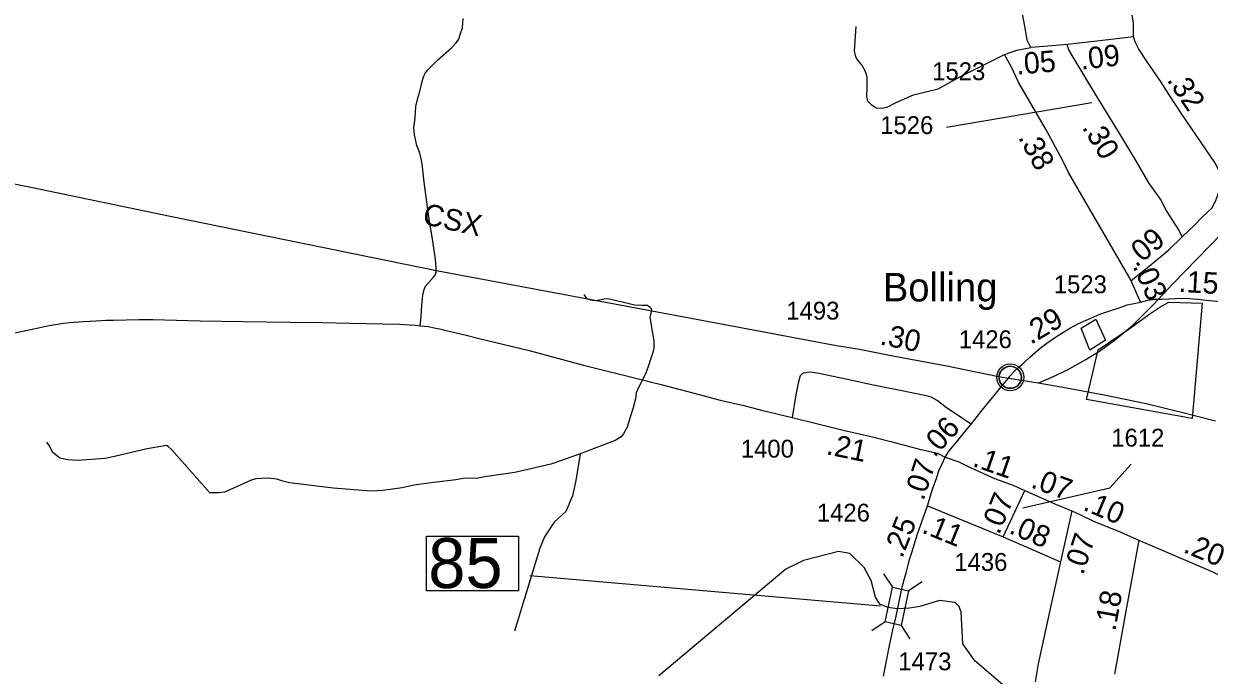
# Model space of a CAD drawing. Extents: x 2290615 to 2522933, y 819489 to 1012715.
# Drawn here: x 2377563 to 2385868, y 989250 to 993811 of the extents above; entities that cross this region are included whole.
import ezdxf

# ---------------------------------------------------------------- set-up
doc = ezdxf.new("R2010")
doc.units = 0
for name, color, linetype in [('Exist Boundary Political City Limit New', 7, 'Continuous'), ('Exist Boundary Political City Limit Old', 7, 'Continuous'), ('Exist Civil Demographics City Label', 7, 'Continuous'), ('Exist Civil Demographics Community CELL', 7, 'Continuous'), ('Exist Hydrographic Creek Single Shore', 7, 'Continuous'), ('Exist Railroad Mainline', 7, 'Continuous'), ('Exist Railroad Mainline Label', 7, 'Continuous'), ('Exist Road Non-System Type 51', 7, 'Continuous'), ('Exist Road Secondary Mileage Hundredths English Label', 7, 'Continuous'), ('Exist Road Secondary Mileage Tenths English Label', 7, 'Continuous'), ('Exist Road Secondary Structure Standard Bridge CELL', 7, 'Continuous'), ('Exist Road Secondary Structure Standard Bridge Number Label', 7, 'Continuous'), ('Exist Road Secondary Type 51 Attributed', 7, 'Continuous'), ('Exist Road Secondary Type 51 Number Label', 7, 'Continuous'), ('Map Preparation Boundary City Limit Buffer Line', 7, 'Continuous')]:
    doc.layers.add(name, color=color, linetype=linetype)

msp = doc.modelspace()

# ---------------------------------------------------------------- linework, layer by layer
at = {"layer": 'Exist Boundary Political City Limit New'}
for points in [[(2385584.2, 991862), (2385818.4, 991856), (2385747.9, 991048.3), (2385009.2, 991181), (2385090.8, 991527.1), (2385307.2, 991674.3), (2385452.8, 991779.2), (2385521.6, 991826.1), (2385584.2, 991862)], [(2385074.3, 991742.2), (2385141.2, 991595.5), (2385031, 991526.2), (2384969.9, 991680.3), (2385074.3, 991742.2)]]:
    msp.add_lwpolyline(points, dxfattribs=at)
at = {"layer": 'Exist Boundary Political City Limit Old'}
for points in [[(2385584.2, 991862), (2385818.4, 991856), (2385747.9, 991048.3), (2385009.2, 991181), (2385090.8, 991527.1), (2385307.2, 991674.3), (2385452.8, 991779.2), (2385521.6, 991826.1), (2385584.2, 991862)], [(2385074.3, 991742.2), (2385141.2, 991595.5), (2385031, 991526.2), (2384969.9, 991680.3), (2385074.3, 991742.2)]]:
    msp.add_lwpolyline(points, dxfattribs=at)
at = {"layer": 'Exist Civil Demographics Community CELL'}
msp.add_lwpolyline([(2384396.5, 991348.2), (2384397.4, 991353.8), (2384399.2, 991360.4), (2384402.1, 991367.6), (2384405.1, 991373.3), (2384408.4, 991379.1), (2384412.2, 991384.2), (2384416.1, 991388.6), (2384420.7, 991393.2), (2384426.2, 991397.7), (2384431.7, 991401.4), (2384436.6, 991404.3), (2384441.6, 991406.7), (2384447.1, 991409), (2384452.7, 991410.8), (2384457, 991412), (2384461.9, 991412.7), (2384466, 991413.5), (2384472.4, 991413.7), (2384476.8, 991413.6), (2384482.5, 991413.3), (2384487.4, 991412.6), (2384492.3, 991411.6), (2384497.3, 991410.2), (2384502.5, 991408.3), (2384509.1, 991405.4), (2384515.4, 991401.9), (2384520.4, 991398.3), (2384525.6, 991394.3), (2384528.9, 991391.2), (2384533, 991386.8), (2384536.9, 991382.1), (2384540, 991377.5), (2384543.1, 991372.5), (2384545.6, 991367.3), (2384547.6, 991362.3), (2384549.2, 991357.3), (2384550.4, 991352.7), (2384551.5, 991346.7), (2384552.2, 991342), (2384552.4, 991336), (2384552.2, 991330.2), (2384551.7, 991324.5), (2384550.7, 991319), (2384549.1, 991312.9), (2384547.2, 991307), (2384544.9, 991301.9), (2384541.7, 991295.9), (2384538.5, 991290.6), (2384535, 991285.9), (2384530.8, 991281.2), (2384525.5, 991276.2), (2384520.5, 991272.1), (2384515.5, 991268.7), (2384511.1, 991266.2), (2384504.3, 991262.9), (2384497.2, 991260.2), (2384491.2, 991258.7), (2384484.6, 991257.4), (2384480.2, 991257), (2384475.7, 991256.7), (2384470.1, 991256.7), (2384465.8, 991257.1), (2384460.2, 991257.9), (2384454.3, 991259.2), (2384449.7, 991260.5), (2384444.5, 991262.3), (2384439.9, 991264.3), (2384436, 991266.6), (2384429.2, 991270.6), (2384423.6, 991274.9), (2384418.7, 991279.4), (2384414.3, 991284.3), (2384411.1, 991288.2), (2384408.1, 991292.4), (2384404, 991299.5), (2384402.3, 991303), (2384400.6, 991307.1), (2384398, 991315.3), (2384396.5, 991322.3), (2384395.8, 991327.5), (2384395.4, 991333.8), (2384395.4, 991338.5), (2384395.9, 991344.9)], close=True, dxfattribs=at)
for centre, radius in [((2384474.1, 991335.8), 94.3), ((2384473.8, 991336.1), 76.7)]:
    msp.add_circle(centre, radius, dxfattribs=at)
at = {"layer": 'Exist Hydrographic Creek Single Shore'}
msp.add_lwpolyline([(2384438.4, 989170.3), (2384226.5, 989351.6), (2384141.4, 989469.6), (2384130.7, 989690.7), (2384116.4, 989732.4), (2384089, 989758.5), (2383978.2, 989774.2), (2383840.1, 989731.1), (2383767.1, 989720.7), (2383685, 989715.5), (2383615.9, 989724.6), (2383559.8, 989748.1), (2383531.2, 989797.7), (2383498.6, 989912.4), (2383451.6, 990005), (2383351.3, 990101.6), (2383270.5, 990115.9), (2383025.5, 990054), (2382901.4, 989993.1), (2382011.5, 989247.3)], dxfattribs=at)
at = {"layer": 'Exist Railroad Mainline'}
msp.add_lwpolyline([(2376970.3, 992795.9), (2377624.1, 992664.5), (2378588.6, 992463.4), (2379653.3, 992247.4), (2380467.4, 992082.3), (2382399.8, 991719.9), (2383255.8, 991557.4), (2383418.1, 991533.4), (2383650.8, 991486.6), (2384029.7, 991415.7), (2384390.6, 991342.5), (2384669.2, 991296.1), (2384867.5, 991262.8), (2385132.2, 991212.3), (2385425, 991152.1), (2385655.6, 991097.3), (2385912.5, 991030.6)], dxfattribs=at)
at = {"layer": 'Exist Road Non-System Type 51'}
for points in [[(2380340.3, 991695.8), (2380347.7, 991759.8), (2380352.3, 991841.6), (2380360.3, 991911.9), (2380368.4, 991951), (2380377.6, 991974.1), (2380431.6, 992033.4), (2380446.5, 992050.7), (2380452.3, 992072.6), (2380453.4, 992103.5), (2380448.8, 992163.4), (2380423.5, 992318.6), (2380406.2, 992426.9), (2380368.3, 992701.7), (2380354.5, 992830.3), (2380345.3, 992876.4), (2380333.8, 992919), (2380317.7, 992958.2), (2380301.6, 993032.7), (2380297, 993084.5), (2380303.9, 993133.7), (2380307.4, 993187.8), (2380309.7, 993231.6), (2380325.8, 993298.4), (2380337.3, 993336.4), (2380349.9, 993389), (2380361.4, 993432.8), (2380373, 993460.4), (2380394.8, 993489.2), (2380418.9, 993514.2), (2380464.9, 993559.1), (2380560.5, 993643.2), (2380593.8, 993676.6), (2380612.2, 993703.8), (2380621.4, 993736.1), (2380637.5, 993782.1), (2380641, 993846.6)], [(2383392.3, 993790.8), (2383380.6, 993618.8), (2383386.9, 993590.9), (2383395.1, 993571), (2383407.5, 993553.1), (2383437.8, 993515.5), (2383454.4, 993483.8), (2383468.9, 993441.9), (2383470, 993361.9), (2383466.7, 993300), (2383475.2, 993270.1), (2383497.5, 993248.4), (2383533.7, 993222.9), (2383573.7, 993219.3), (2383611.7, 993225.9), (2383675.3, 993258.7), (2383796.6, 993312.3), (2383892.1, 993335.7), (2383970, 993354.7), (2384124.7, 993440.7), (2384434.6, 993594.7)], [(2383392.3, 993790.8), (2383380.6, 993618.8), (2383386.9, 993590.9), (2383395.1, 993571), (2383407.5, 993553.1), (2383437.8, 993515.5), (2383454.4, 993483.8), (2383468.9, 993441.9), (2383470, 993361.9), (2383466.7, 993300), (2383475.2, 993270.1), (2383497.5, 993248.4), (2383533.7, 993222.9), (2383573.7, 993219.3), (2383611.7, 993225.9), (2383675.3, 993258.7), (2383796.6, 993312.3), (2383892.1, 993335.7), (2383970, 993354.7), (2384124.7, 993440.7), (2384434.6, 993594.7)], [(2384673.2, 991296.3), (2384764.6, 991337.4), (2384875.9, 991388.9), (2384999, 991458.6), (2385100.2, 991517.7), (2385211.1, 991599.4), (2385329.7, 991698.9), (2385473.7, 991840.7), (2385609.9, 991988.6), (2385959.1, 992345.2)], [(2381486.6, 991915.2), (2381506.2, 991886.5), (2381532.6, 991877.2), (2381559.1, 991872.6), (2381597.1, 991878.4), (2381630.5, 991885.3), (2381654.6, 991886.5), (2381684.6, 991880.7), (2381795.1, 991855.4), (2381842.3, 991843.8), (2381896.1, 991840.9), (2381934, 991840.9), (2381952.5, 991827.1), (2381960.5, 991809.8), (2381955.9, 991785.6), (2381949, 991756.8), (2381953.6, 991726.9), (2381976.6, 991592.1), (2381976.6, 991542.6), (2381969.7, 991510.3), (2381957.1, 991467.7), (2381940.9, 991418.2), (2381924.8, 991371), (2381898.7, 991318.3), (2381874.2, 991275), (2381853.5, 991227.8), (2381847.8, 991186.3), (2381830.5, 991116), (2381814.4, 991064.2), (2381790.2, 990987), (2381766, 990941), (2381747.6, 990920.2), (2381707.5, 990894), (2381461.1, 990799.8)], [(2381461.1, 990799.8), (2381330.4, 990753.6), (2381255.6, 990727.1), (2381116.6, 990696), (2381003.8, 990669.5), (2380938.2, 990659.2), (2380793.2, 990638.4), (2380732.2, 990626.9), (2380655.7, 990629.6), (2380591.2, 990619.2), (2380417.4, 990596.2), (2380347.2, 990588.1), (2380298.9, 990581.2), (2380213.7, 990561.6), (2380079.5, 990544.5), (2379995.5, 990538.7), (2379730.7, 990559.4), (2379425.1, 990596.3), (2379377.9, 990607.9), (2379336.5, 990621.7), (2379276.6, 990629.7), (2379231.7, 990628.6), (2379188.4, 990624.2), (2379151.6, 990613.8), (2379006.6, 990548.1), (2378969.8, 990532), (2378932.9, 990526.3), (2378867.3, 990527.4), (2378601.9, 990827.7), (2378574.3, 990850.7), (2378562.8, 990858.8), (2378429.3, 990835.7), (2378198.4, 990781.7), (2378133.9, 990767.9), (2377941, 990753.9), (2377873.1, 990758.5), (2377816.7, 990768.9), (2377766, 990811.5), (2377743, 990855.2), (2377724.6, 990881.7)], [(2381461.1, 990799.8), (2381430.5, 990612.7), (2381407.5, 990506.7), (2381361.5, 990396.2), (2381278.6, 990322.4), (2381211.8, 990218.8), (2381179.6, 990140.5), (2381000.3, 989558.7)]]:
    msp.add_lwpolyline(points, dxfattribs=at)
at = {"layer": 'Exist Road Secondary Structure Standard Bridge CELL'}
for p, q in [((2383587.3, 989960.9), (2383648.8, 989865.8)), ((2383857, 989903), (2383762, 989841.6)), ((2383598.8, 989623), (2383503.8, 989561.6)), ((2383709.5, 989599.3), (2383771, 989504.3))]:
    msp.add_line(p, q, dxfattribs=at)
msp.add_lwpolyline([(2383762, 989841.6), (2383710, 989599.2), (2383596.8, 989623.5), (2383648.8, 989865.8)], close=True, dxfattribs=at)
at = {"layer": 'Exist Road Secondary Structure Standard Bridge Number Label'}
msp.add_line((2383566, 989732.9), (2381107.8, 989946.6), dxfattribs=at)
msp.add_lwpolyline([(2380384.7, 990223.2), (2381028.9, 990223.2), (2381028.9, 989840.9), (2380384.7, 989840.9)], close=True, dxfattribs=at)
at = {"layer": 'Exist Road Secondary Type 51 Attributed'}
for p, q in [((2384424.9, 990219.3), (2384575.2, 990544)), ((2383893.7, 990435.8), (2384424.9, 990219.3)), ((2384424.9, 990219.3), (2384826.1, 990045.1))]:
    msp.add_line(p, q, dxfattribs=at)
for points in [[(2385337.5, 993719.4), (2385338.4, 993815.8), (2385308.5, 993995.5), (2385299.3, 994189), (2385285.5, 994387.1), (2385264.8, 994664.6), (2385253.8, 994880.7)], [(2384619.3, 993644.3), (2384591.9, 993696.5), (2384578.1, 993781.7), (2384548.2, 993937.6)], [(2384874.8, 993666.5), (2384709.3, 993652.7), (2384619.3, 993644.3)], [(2385337.5, 993719.4), (2385121.1, 993694.1), (2384874.8, 993666.5)], [(2385677.8, 992318.7), (2385654.8, 992367.7), (2385567.3, 992506), (2385525.9, 992582), (2385445.3, 992697.2), (2385358, 992847.3), (2385247.7, 993029.1), (2385092.4, 993282.1), (2384981.9, 993465.2), (2384921.1, 993565), (2384884.3, 993627.2), (2384875.1, 993657.2), (2384874.8, 993666.5)], [(2385677.8, 992318.7), (2385763, 992399.4), (2385820.5, 992459.3), (2385889.3, 992522.9), (2385916.9, 992580.5), (2385937.7, 992638.1), (2385946.9, 992716.4), (2385937.7, 992780.9), (2385907.7, 992838.5), (2385781.1, 993025), (2385675.6, 993178.5), (2385588.1, 993312.1), (2385526, 993408.8), (2385429.5, 993551.3), (2385374.3, 993631.9), (2385349, 993684.9), (2385337.5, 993719.4)], [(2385321, 992014.7), (2384881.9, 992770.7), (2384839.6, 992856.3), (2384725.6, 993067.1), (2384533.6, 993397.1), (2384479.5, 993512.2), (2384434.6, 993594.7), (2384519.7, 993625.7), (2384619.3, 993644.3)], [(2385321, 992014.7), (2385447.6, 992113.7), (2385585.7, 992228.9), (2385677.8, 992318.7)], [(2385387, 991862.9), (2385330.2, 991989.3), (2385321, 992014.7)], [(2384461.2, 991330.7), (2384471.7, 991343.1), (2384503.9, 991377.7), (2384537.3, 991409.9), (2384568.4, 991437.5), (2384611, 991477.9), (2384647.8, 991510.1), (2384683.5, 991540.1), (2384730.7, 991574.6), (2384790.1, 991616.7), (2384854.6, 991655.9), (2384897.2, 991681.2), (2384947.8, 991710), (2384990.4, 991728.4), (2385037.6, 991750.3), (2385100.9, 991776.8), (2385171.8, 991800.7), (2385236.2, 991821.5), (2385292.6, 991842.2), (2385328.3, 991849.1), (2385387, 991862.9)], [(2385387, 991862.9), (2385438.8, 991875.6), (2385486, 991882.5), (2385538.9, 991883.7), (2385631, 991888.3), (2385688.6, 991889.4), (2385730.7, 991888.3), (2385786, 991883.7), (2385849.3, 991876.8), (2385918.3, 991869.9), (2385993.1, 991865.3), (2386040.3, 991860.7), (2386127.2, 991850.6), (2386162.4, 991846.9)], [(2377489.3, 991644.9), (2377667.4, 991681.5), (2377706.5, 991691.9), (2377754.9, 991700), (2377800.9, 991708), (2377842.3, 991713.8), (2377886.1, 991719.5), (2377979.2, 991726.4), (2378028.6, 991729.9), (2378067.8, 991732.2), (2378141.2, 991735.6), (2378193, 991736.8), (2378372.3, 991740.2), (2378467.8, 991740.2), (2378798.9, 991732.1), (2379101.4, 991727.5), (2379429.1, 991722.9), (2379649.6, 991719.4), (2379848.7, 991716), (2380194.9, 991706.8), (2380262.8, 991703.3), (2380307.7, 991699.9), (2380340.3, 991695.8), (2380399.4, 991690.7), (2380439.7, 991682.6), (2380476.6, 991674.5), (2380522.6, 991663), (2380653.4, 991633.2), (2380745.5, 991610.2), (2381103, 991524.1), (2381484.7, 991421.7), (2381898.7, 991318.3), (2381951.5, 991304.6), (2382029.8, 991286.1), (2382295.2, 991216), (2382441.4, 991175.7), (2382607.2, 991137.7), (2382741.4, 991104.6), (2382946.9, 991054.1)], [(2384199.3, 991008.3), (2384027.7, 991122.8), (2383961.6, 991173.2), (2383921.1, 991196.2), (2383886.4, 991206.6), (2383597.8, 991265.3), (2383503.8, 991283.6), (2383333, 991319.5), (2383134, 991362.8), (2383089.7, 991370), (2383063.9, 991371.6), (2383040.4, 991367.3), (2383025.5, 991364.1), (2383013.9, 991358), (2383003.5, 991346.9), (2382997.7, 991329), (2382988, 991295.3), (2382972.5, 991214), (2382946.9, 991054.1)], [(2384199.3, 991008.3), (2384276.3, 991105.3), (2384363.8, 991211.3), (2384423.7, 991286.2), (2384461.2, 991330.7)], [(2382946.9, 991054.1), (2383134.7, 991008), (2383303.5, 990965.5), (2383499.2, 990921.7), (2383638.5, 990887.2), (2383848.8, 990829.7), (2383963.9, 990804.4), (2384019.1, 990776.8)], [(2384019.1, 990776.8), (2384046.5, 990821.2), (2384097.1, 990881.1), (2384143.2, 990941), (2384199.3, 991008.3)], [(2383893.7, 990435.8), (2383932.7, 990560.2), (2383956.9, 990628.2), (2383974.2, 990681.2), (2383993.7, 990724.9), (2384019.1, 990776.8)], [(2384019.1, 990776.8), (2384113.1, 990743.3), (2384179.9, 990712.2), (2384362.6, 990627.2), (2384498.4, 990578.8), (2384575.2, 990544)], [(2384575.2, 990544), (2384791.9, 990448.7), (2384905.4, 990400.7)], [(2383714.2, 989857.1), (2383733.8, 989928), (2383745.3, 989967.2), (2383759.1, 990023.2), (2383770.6, 990068.1), (2383790.2, 990123.4), (2383822.3, 990232.5), (2383893.7, 990435.8)], [(2384905.4, 990400.7), (2384826.1, 990045.1)], [(2384905.4, 990400.7), (2384962.5, 990376.6), (2385062.6, 990327.1), (2385232.9, 990259.1), (2385375.1, 990195.5)], [(2385375.1, 990195.5), (2385278.8, 989672.3), (2385204.2, 989257.4)], [(2385375.1, 990195.5), (2385864.1, 989985.3), (2386019.5, 989912.8), (2386247.2, 989824.8), (2386341.9, 989803.8)], [(2384826.1, 990045.1), (2384759.8, 989747.4), (2384708.5, 989513), (2384669.4, 989330.2), (2384647.6, 989205)], [(2383585.5, 989242.7), (2383613.1, 989386.7), (2383626.9, 989446.6), (2383651.1, 989569.2), (2383671.8, 989652.2), (2383702.8, 989799), (2383714.2, 989857.1)]]:
    msp.add_lwpolyline(points, dxfattribs=at)
at = {"layer": 'Exist Road Secondary Type 51 Number Label'}
msp.add_line((2385045.2, 993258.1), (2384028.2, 993084.9), dxfattribs=at)
msp.add_lwpolyline([(2384561.9, 990421.3), (2385170.4, 990562.9), (2385321.3, 990728)], dxfattribs=at)
at = {"layer": 'Map Preparation Boundary City Limit Buffer Line'}
for points in [[(2385584.2, 991862), (2385818.4, 991856), (2385747.9, 991048.3), (2385009.2, 991181), (2385090.8, 991527.1), (2385307.2, 991674.3), (2385452.8, 991779.2), (2385521.6, 991826.1), (2385584.2, 991862)], [(2385074.3, 991742.2), (2385141.2, 991595.5), (2385031, 991526.2), (2384969.9, 991680.3), (2385074.3, 991742.2)]]:
    msp.add_lwpolyline(points, dxfattribs=at)

# ---------------------------------------------------------------- texts
at = {"layer": 'Exist Civil Demographics City Label'}
msp.add_text('Bolling', height=200, rotation=360, dxfattribs=at).set_placement((2383581.3, 991866.9))
at = {"layer": 'Exist Railroad Mainline Label'}
msp.add_text('CSX', height=150, rotation=347.52886, dxfattribs=at).set_placement((2380350.2, 992410.6))
at = {"layer": 'Exist Road Secondary Mileage Hundredths English Label'}
for s, rotation, p in [('.03', 294.19984, (2385329.2, 992113.5)), ('.29', 30.75265, (2384618.1, 991562.3)), ('.11', 337.81923, (2383848, 990251.1)), ('.08', 336.53377, (2384457.4, 990247.7)), ('.18', 79.80997, (2385209.8, 989554.7))]:
    msp.add_text(s, height=150, rotation=rotation, dxfattribs=at).set_placement(p)
at = {"layer": 'Exist Road Secondary Mileage Tenths English Label'}
for s, rotation, p in [('.09', 6.40318, (2384971.7, 993489)), ('.05', 4.75393, (2384520.2, 993454.1)), ('.32', 304.15851, (2385567.1, 993416.9)), ('.30', 301.27109, (2384973.9, 993085)), ('.38', 298.39604, (2384527.1, 993015.4)), ('.09', 39.82494, (2385355.6, 992101.1)), ('.15', 356.80823, (2385650.8, 991934.3)), ('.30', 348.32639, (2383555.3, 991567.2)), ('.06', 47.85253, (2383942.7, 990769.4)), ('.21', 348.32639, (2383179.1, 990798.5)), ('.07', 71.70434, (2383866, 990466.3)), ('.11', 340.74224, (2384203.8, 990716)), ('.07', 340.10277, (2384611.5, 990566.7)), ('.07', 67.3129, (2384395.3, 990228.8)), ('.10', 336.96888, (2384976.4, 990410.7)), ('.25', 68.31422, (2383717, 990063.6)), ('.07', 71.74542, (2384984.2, 989946.9)), ('.20', 337.57657, (2385678.8, 990114))]:
    msp.add_text(s, height=150, rotation=rotation, dxfattribs=at).set_placement(p)
at = {"layer": 'Exist Road Secondary Structure Standard Bridge Number Label'}
msp.add_text('85', height=350, dxfattribs=at).set_placement((2380397.3, 989860.7))
at = {"layer": 'Exist Road Secondary Type 51 Number Label'}
for s, p in [('1523', (2383927.2, 993415.9)), ('1526', (2383563.1, 993038.8)), ('1523', (2384779, 991924.5)), ('1493', (2382905.4, 991740)), ('1426', (2384113.4, 991539.7)), ('1612', (2385181.5, 990850.9)), ('1400', (2382586.4, 990773.9)), ('1426', (2383119.3, 990325.9)), ('1436', (2384082.1, 989980.7)), ('1473', (2383689.9, 989285.1))]:
    msp.add_text(s, height=125, dxfattribs=at).set_placement(p)

doc.saveas('drawing.dxf')
